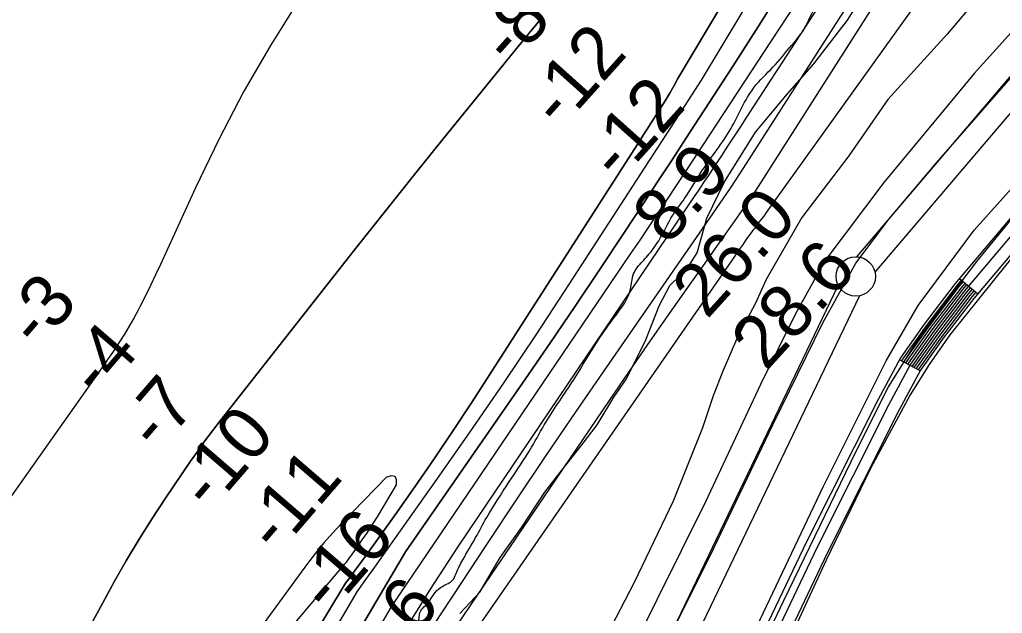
# Model space of a CAD drawing. Extents: x 3324104 to 3361979, y 612876 to 638273.
# Drawn here: x 3339241 to 3340489, y 622586 to 623340 of the extents above; entities that cross this region are included whole.
import ezdxf

# ---------------------------------------------------------------- set-up
doc = ezdxf.new("R2010")
doc.units = 0
for name, color, linetype in [('V-FLOD-BASE', 7, 'Continuous'), ('V-LEVE-TOET', 7, 'Continuous'), ('V-RIVR-EDGE', 7, 'Continuous'), ('V-RIVR-RANG', 7, 'Continuous'), ('V-ROAD-CNTR', 7, 'Continuous'), ('V-SITE-VEGE', 7, 'Continuous'), ('V-SURV-LINE', 7, 'Continuous'), ('V-TOPO-DPTH', 7, 'Continuous'), ('V-TOPO-MAJR', 7, 'Continuous'), ('V-TOPO-MINR', 7, 'Continuous'), ('V-TOPO-SHOR', 7, 'Continuous'), ('V-TOPO-WATR', 7, 'Continuous')]:
    doc.layers.add(name, color=color, linetype=linetype)

msp = doc.modelspace()

# ---------------------------------------------------------------- linework, layer by layer
at = {"layer": 'V-FLOD-BASE'}
msp.add_lwpolyline([(3339312.7, 620882.4), (3339404.9, 621089.8), (3339494.8, 621286.7), (3339586.4, 621493.4), (3339673.4, 621686.8), (3339741.3, 621847.5), (3339817, 622012.2), (3339917.6, 622243.4), (3340054, 622530.2), (3340122.8, 622669), (3340197.7, 622825.3), (3340261.4, 622955.1), (3340303.3, 623031), (3340345.5, 623087.2), (3340405.7, 623158.4), (3340514.4, 623282.9), (3340676.8, 623471.8)], dxfattribs=at)
at = {"layer": 'V-LEVE-TOET'}
for points in [[(3339416.8, 620890.1), (3339510.6, 621102.4), (3339609.6, 621324.5), (3339704.8, 621540.3), (3339774.2, 621702.3), (3339864.8, 621898.5), (3339953.2, 622091.1), (3340054.1, 622308.9), (3340149.8, 622511.3), (3340261.8, 622746.5), (3340341.6, 622906.9), (3340382.1, 622977.2), (3340453.4, 623072.9), (3340537.4, 623166.2), (3340664.9, 623312.1), (3340768.6, 623435.3)], [(3340579.5, 623411.9), (3340453.5, 623271.6), (3340338.8, 623133.2), (3340263.9, 623034), (3340226.3, 622965.8), (3340182, 622876.5), (3340112.2, 622727.8), (3339988.7, 622478.8), (3339907.9, 622310.7), (3339844.7, 622171.7), (3339774.1, 622016.8), (3339706.5, 621866.6), (3339613.4, 621655), (3339536.3, 621491.7), (3339464, 621327.6), (3339384.4, 621148.9), (3339298.2, 620958.3), (3339251.4, 620856.3)]]:
    msp.add_lwpolyline(points, dxfattribs=at)
at = {"layer": 'V-RIVR-EDGE'}
msp.add_spline([(3338849.5, 620833.7), (3338863.9, 620858.4), (3338873.2, 620877), (3338879.5, 620892.9), (3338887.7, 620911.1), (3338889.2, 620920.8), (3338889.3, 620930.9), (3338889.3, 620936.7), (3338892.8, 620944.8), (3338909.2, 620979.3), (3338928.6, 621017.7), (3338934.9, 621032.8), (3338933, 621036.3), (3338935.3, 621042.1), (3338955.2, 621075.8), (3338956.3, 621080), (3338951.3, 621082.4), (3338952.5, 621087.4), (3338954, 621094.8), (3338957.5, 621099.4), (3338963, 621104.8), (3338961.4, 621110.7), (3338960.7, 621117.6), (3338962.2, 621121.5), (3338980.9, 621151.3), (3338987.5, 621160.2), (3338994.6, 621173), (3339001.6, 621180.4), (3339008.6, 621185.8), (3339012.8, 621191.6), (3339013.6, 621197), (3339013.2, 621200.9), (3339009.8, 621206.7), (3339008.2, 621211.8), (3339009, 621213.7), (3339012.5, 621216.8), (3339014.8, 621221.1), (3339014.9, 621226.5), (3339018.4, 621227.2), (3339028, 621227.6), (3339031.2, 621232.3), (3339035.1, 621243.9), (3339039.8, 621256.3), (3339042.9, 621268.7), (3339045.6, 621270.2), (3339049.9, 621273.7), (3339052.6, 621276.8), (3339055.3, 621283.8), (3339058.5, 621297.7), (3339063.5, 621308.2), (3339066.3, 621319), (3339072.9, 621338), (3339074.5, 621340.7), (3339071.8, 621346.2), (3339071.4, 621350.8), (3339070.6, 621355.9), (3339070.6, 621360.9), (3339074.6, 621374.9), (3339080, 621383.4), (3339091.3, 621402), (3339101.8, 621418.6), (3339106.9, 621432.2), (3339108.9, 621448.5), (3339114.7, 621460.9), (3339121.7, 621472.9), (3339138.1, 621494.5), (3339146.6, 621512.7), (3339150.9, 621515.8), (3339154, 621517), (3339157.5, 621520.5), (3339162.2, 621524.7), (3339162.6, 621530.9), (3339163, 621535.2), (3339166.5, 621539.4), (3339173.9, 621548.4), (3339187.9, 621560), (3339202.3, 621575.4), (3339208.5, 621582), (3339220.9, 621601.4), (3339227.2, 621611.8), (3339228.3, 621618.4), (3339232.6, 621620.7), (3339234.6, 621627.7), (3339234.6, 621632.4), (3339233.8, 621643.2), (3339233.9, 621652.9), (3339235, 621660.7), (3339237.8, 621668.8), (3339245.6, 621681.6), (3339256.4, 621692), (3339259.6, 621702.1), (3339260.4, 621709.5), (3339267.8, 621721.9), (3339275.9, 621735.4), (3339287.3, 621761), (3339293.1, 621772.6), (3339304, 621793.5), (3339318, 621822.9), (3339329.7, 621836.9), (3339335.2, 621843.1), (3339330.5, 621848.9), (3339330.5, 621851.6), (3339333.3, 621855.9), (3339336.4, 621859.7), (3339342.2, 621865.5), (3339347.6, 621869.8), (3339357, 621888), (3339376.1, 621923.6), (3339382.7, 621941.8), (3339386.6, 621950.8), (3339393.2, 621962.8), (3339404.5, 621981.7), (3339427.1, 622013.9), (3339446.2, 622044.5), (3339464.1, 622073.5), (3339479.3, 622102.9), (3339498.8, 622140.9), (3339514.4, 622174.6), (3339531.9, 622205.2), (3339537.7, 622216), (3339537.7, 622219.9), (3339534.7, 622225.7), (3339534.7, 622228.8), (3339534.7, 622231.9), (3339539.7, 622235), (3339547.5, 622242.8), (3339556.8, 622254), (3339556.8, 622259.8), (3339555.7, 622266.4), (3339558.4, 622271.4), (3339563.9, 622273.7), (3339568.6, 622287.7), (3339574, 622293.9), (3339576.3, 622298.5), (3339576.4, 622305.1), (3339577.9, 622309.8), (3339583.4, 622315.6), (3339592.7, 622321.8), (3339605.1, 622339.6), (3339611, 622347.3), (3339621.1, 622355.4), (3339623.8, 622361.6), (3339624.2, 622367.4), (3339624.6, 622374.8), (3339628.1, 622381.4), (3339634.7, 622394.2), (3339652.6, 622417.8), (3339667, 622436.8), (3339680.3, 622456.9), (3339694.3, 622479), (3339705.2, 622499.1), (3339708.7, 622510.7), (3339714.6, 622523.5), (3339723.1, 622538.6), (3339729.4, 622550.2), (3339737.9, 622567.3), (3339738.7, 622571.9), (3339742.2, 622573.5), (3339746.9, 622573.8), (3339748.4, 622577.7), (3339749.2, 622585.1), (3339752, 622591.3), (3339757.8, 622596.7), (3339769.1, 622612.6), (3339778.4, 622620.3), (3339791.2, 622628), (3339795.5, 622636.5), (3339804.1, 622654), (3339820.4, 622682.2), (3339834.5, 622707.8), (3339891.3, 622796.9), (3339910, 622829.4), (3339944.6, 622882.4), (3339978.1, 622936.2), (3339998.7, 622964.9), (3340017.1, 622997.8), (3340021, 623017.2), (3340025.7, 623025.3), (3340038.9, 623040.4), (3340052.9, 623059.4), (3340070.8, 623091.9), (3340085.6, 623112.8), (3340108.6, 623149.2), (3340144.4, 623201.5), (3340174, 623254.2), (3340198.1, 623280.1), (3340221.4, 623307.2), (3340237, 623327.3), (3340244.4, 623342), (3340256.8, 623363.3), (3340272.8, 623384.6), (3340289.1, 623408.2), (3340302.8, 623428.7), (3340311.7, 623438.8), (3340319.5, 623450.4), (3340319.5, 623457.8), (3340325, 623465.9), (3340333.5, 623476.7), (3340341.3, 623483.3), (3340352.2, 623496.5), (3340367.4, 623520.1), (3340394.2, 623560), (3340400.1, 623574.3), (3340403.2, 623588.6), (3340409.1, 623600.7), (3340420.7, 623609.9), (3340437, 623624.6), (3340446.4, 623639.7), (3340451.1, 623650.6), (3340458.1, 623662.2), (3340477.1, 623683.9), (3340488, 623697)], degree=3, dxfattribs=at)
at = {"layer": 'V-ROAD-CNTR'}
for p, q in [((3340457.5, 622991.7), (3340434.6, 623011)), ((3340384.8, 622893.9), (3340358.4, 622908.1))]:
    msp.add_line(p, q, dxfattribs=at)
for points in [[(3340841.4, 623447.3), (3340749.1, 623337.6), (3340645.2, 623213.8), (3340452.8, 622986.1), (3340414.2, 622935.4), (3340385.2, 622894.7), (3340357.9, 622843.7), (3340267.3, 622663.5), (3340044.5, 622195.6), (3339766.5, 621575.5), (3339542.5, 621063.3), (3339452.6, 620864.7), (3339341.9, 620612.8)], [(3340726.1, 623356.9), (3340622.3, 623233.1), (3340429.4, 623004.9), (3340390, 622953.2), (3340359.7, 622910.5), (3340331.3, 622857.5), (3340240.4, 622676.7), (3340017.2, 622208.2), (3339739.1, 621587.6), (3339515.1, 621075.5), (3339425.2, 620876.9), (3339314.4, 620624.9)], [(3340737.6, 623347.3), (3340633.8, 623223.5), (3340441.1, 622995.5), (3340402.1, 622944.3), (3340372.4, 622902.6), (3340344.6, 622850.6), (3340253.9, 622670.1), (3340030.9, 622201.9), (3339752.8, 621581.6), (3339528.8, 621069.4), (3339438.9, 620870.8), (3339328.1, 620618.8)], [(3340436.9, 623009.1), (3340431.7, 623003), (3340392.5, 622951.4), (3340362.2, 622908.9), (3340361, 622906.7)], [(3340439.1, 623007.1), (3340434.1, 623001.1), (3340394.9, 622949.7), (3340364.8, 622907.3), (3340363.7, 622905.2)], [(3340441.4, 623005.2), (3340436.4, 622999.2), (3340397.3, 622947.9), (3340367.3, 622905.8), (3340366.3, 622903.8)], [(3340443.7, 623003.3), (3340438.7, 622997.4), (3340399.7, 622946.1), (3340369.9, 622904.2), (3340368.9, 622902.4)], [(3340446, 623001.3), (3340441.1, 622995.5), (3340402.1, 622944.3), (3340372.4, 622902.6), (3340371.6, 622901)], [(3340448.3, 622999.4), (3340443.4, 622993.6), (3340404.5, 622942.5), (3340375, 622901), (3340374.2, 622899.6)], [(3340450.6, 622997.5), (3340445.8, 622991.7), (3340407, 622940.8), (3340377.6, 622899.4), (3340376.9, 622898.1)], [(3340452.9, 622995.5), (3340448.1, 622989.9), (3340409.4, 622939), (3340380.1, 622897.8), (3340379.5, 622896.7)], [(3340455.2, 622993.6), (3340450.4, 622988), (3340411.8, 622937.2), (3340382.7, 622896.3), (3340382.2, 622895.3)]]:
    msp.add_lwpolyline(points, dxfattribs=at)
at = {"layer": 'V-SITE-VEGE'}
for p, q in [((3340292.6, 623339.4), (3340341.7, 623417.2)), ((3340476.5, 623390.1), (3340419.2, 623321.6)), ((3340249.7, 623283.9), (3340292.6, 623339.4)), ((3340419.2, 623321.6), (3340343.9, 623238.7)), ((3340216.4, 623245.9), (3340249.7, 623283.9)), ((3340175.8, 623197.4), (3340216.4, 623245.9)), ((3340343.9, 623238.7), (3340294.3, 623167.2)), ((3340136.2, 623134.2), (3340175.8, 623197.4)), ((3340294.3, 623167.2), (3340234.7, 623088.8)), ((3340114, 623088.1), (3340136.2, 623134.2)), ((3340101.7, 623043.9), (3340114, 623088.1)), ((3340234.7, 623088.8), (3340189.1, 623010.2)), ((3340090, 623025.2), (3340101.7, 623043.9)), ((3340080.6, 623015.5), (3340090, 623025.2)), ((3340066.9, 623002.4), (3340080.6, 623015.5)), ((3340189.1, 623010.2), (3340175.7, 622980.2)), ((3340053.6, 622976.6), (3340066.9, 623002.4)), ((3340036.4, 622933.3), (3340053.6, 622976.6)), ((3340175.7, 622980.2), (3340152.8, 622936.9)), ((3340011.9, 622883.8), (3340036.4, 622933.3)), ((3340152.8, 622936.9), (3340134.2, 622893.6)), ((3339995.9, 622860.8), (3340011.9, 622883.8)), ((3340134.2, 622893.6), (3340122.2, 622862.2)), ((3339974.6, 622825.4), (3339995.9, 622860.8)), ((3340122.2, 622862.2), (3340108.6, 622821.6)), ((3339955.7, 622800.4), (3339974.6, 622825.4)), ((3340108.6, 622821.6), (3340071.1, 622728.6)), ((3339930.3, 622768.5), (3339955.7, 622800.4)), ((3339908.4, 622740.1), (3339930.3, 622768.5)), ((3339879.2, 622695.6), (3339908.4, 622740.1)), ((3340071.1, 622728.6), (3340021.5, 622625.3)), ((3339851.5, 622656.8), (3339879.2, 622695.6)), ((3339825.8, 622612.9), (3339851.5, 622656.8)), ((3340021.5, 622625.3), (3339950.6, 622488)), ((3339800.5, 622586), (3339825.8, 622612.9))]:
    msp.add_line(p, q, dxfattribs=at)
at = {"layer": 'V-SURV-LINE'}
for points in [[(3340304.5, 623039), (3341044.9, 623909.4)], [(3341067.8, 623889.9), (3340327.3, 623019.5)], [(3339912.1, 622233.3), (3340280.8, 623002.5)], [(3340307.9, 622989.5), (3339939.2, 622220.3)]]:
    msp.add_lwpolyline(points, dxfattribs=at)
msp.add_circle((3340303, 623014), 25, dxfattribs=at)
at = {"layer": 'V-TOPO-DPTH'}
for points in [[(3340401.8, 623809.5), (3340077.1, 623265.5), (3340072.4, 623256.6), (3340067.5, 623247.7), (3340062.3, 623239), (3340057, 623230.3), (3340042.5, 623207.8), (3340038.3, 623201.1), (3340034, 623194.5), (3340029.8, 623187.9), (3340025.5, 623181.3), (3339815.8, 622854.5), (3339792, 622818.2), (3339767.9, 622782.2), (3339743.3, 622746.5), (3339718.2, 622711.1), (3339679.5, 622657.4), (3339673.5, 622649.1), (3339667.4, 622640.8), (3339661.3, 622632.5), (3339655.3, 622624.3), (3339316.8, 622062.3)], [(3339316.8, 622062.3), (3339655.3, 622624.3), (3339661.3, 622632.5), (3339667.4, 622640.8), (3339673.5, 622649.1), (3339679.5, 622657.4), (3339718.2, 622711.1), (3339743.3, 622746.5), (3339767.9, 622782.2), (3339792, 622818.2), (3339815.8, 622854.5), (3340025.5, 623181.3), (3340029.8, 623187.9), (3340034, 623194.5), (3340038.3, 623201.1), (3340042.5, 623207.8), (3340057, 623230.3), (3340062.3, 623239), (3340067.5, 623247.7), (3340072.4, 623256.6), (3340077.1, 623265.5), (3340401.8, 623809.5)], [(3339739.3, 622578.5), (3339750.8, 622597), (3339762.4, 622615.4), (3339774.1, 622633.7), (3339785.9, 622651.9), (3339797.9, 622670), (3339810, 622688.1), (3340099.2, 623116.7), (3340103.2, 623122.6), (3340107.2, 623128.6), (3340111.1, 623134.5), (3340115.1, 623140.4), (3340124, 623153.9), (3340132.4, 623166.6), (3340140.8, 623179.3), (3340149.1, 623192), (3340157.4, 623204.7), (3340161.9, 623211.8), (3340172.5, 623228), (3340183, 623244.3), (3340193.5, 623260.6), (3340204.1, 623276.8), (3340363.2, 623522.2)], [(3340211.5, 623382.7), (3340179.7, 623331.9), (3340147.4, 623281.5), (3340104.8, 623215.9), (3340087.3, 623189), (3340069.8, 623162.2), (3340052.3, 623135.4), (3340034.7, 623108.6), (3340008.7, 623068.9), (3339977.8, 623022.4), (3339946.8, 622976.1), (3339915.4, 622930), (3339883.8, 622884.1), (3339731.3, 622664.2), (3339344.2, 622006.7), (3339335.7, 621992)], [(3340211.5, 623382.7), (3340179.7, 623331.9), (3340147.4, 623281.5), (3340104.8, 623215.9), (3340087.3, 623189), (3340069.8, 623162.2), (3340052.3, 623135.4), (3340034.7, 623108.6), (3340008.7, 623068.9), (3339977.8, 623022.4), (3339946.8, 622976.1), (3339915.4, 622930), (3339883.8, 622884.1), (3339731.3, 622664.2), (3339344.2, 622006.7), (3339335.7, 621992)], [(3339189.5, 622322.2), (3339317.9, 622544.8), (3339332.4, 622572.2), (3339347.1, 622599.5), (3339361.9, 622626.7), (3339377.2, 622653.6), (3339393, 622680.2), (3339409.5, 622706.4), (3339426.5, 622732.3), (3339458.4, 622779.1), (3339467.5, 622792.2), (3339476.7, 622805.1), (3339486.2, 622817.8), (3339495.9, 622830.4), (3339670.1, 623051.9), (3339706.3, 623097.7), (3339742.6, 623143.4), (3339779.2, 623188.8), (3339816, 623234.2), (3339876.2, 623308.1), (3339882.9, 623316.3), (3339889.7, 623324.6), (3339896.4, 623332.9), (3339903.2, 623341.2)], [(3339903.2, 623341.2), (3339896.4, 623332.9), (3339889.7, 623324.6), (3339882.9, 623316.3), (3339876.2, 623308.1), (3339816, 623234.2), (3339779.2, 623188.8), (3339742.6, 623143.4), (3339706.3, 623097.7), (3339670.1, 623051.9), (3339495.9, 622830.4), (3339486.2, 622817.8), (3339476.7, 622805.1), (3339467.5, 622792.2), (3339458.4, 622779.1), (3339426.5, 622732.3), (3339409.5, 622706.4), (3339393, 622680.2), (3339377.2, 622653.6), (3339361.9, 622626.7), (3339347.1, 622599.5), (3339332.4, 622572.2), (3339317.9, 622544.8), (3339189.5, 622322.2)]]:
    msp.add_lwpolyline(points, dxfattribs=at)
at = {"layer": 'V-TOPO-MAJR'}
msp.add_lwpolyline([(3339801.4, 622536.7), (3340149.5, 623039.5), (3340153.1, 623044.8), (3340156.7, 623049.9), (3340160.4, 623055.1), (3340164.1, 623060.3), (3340170, 623068.6), (3340171.5, 623070.6), (3340173, 623072.6), (3340174.6, 623074.6), (3340176.1, 623076.6), (3340179.7, 623081.5), (3340182.3, 623084.9), (3340184.9, 623088.4), (3340187.4, 623091.8), (3340189.9, 623095.3), (3340609.4, 623680.9)], dxfattribs=at)
at = {"layer": 'V-TOPO-MINR'}
for points in [[(3339316.8, 622062.3), (3339655.3, 622624.3), (3339661.3, 622632.5), (3339667.4, 622640.8), (3339673.5, 622649.1), (3339679.5, 622657.4), (3339718.2, 622711.1), (3339743.3, 622746.5), (3339767.9, 622782.2), (3339792, 622818.2), (3339815.8, 622854.5), (3340025.5, 623181.3), (3340029.8, 623187.9), (3340034, 623194.5), (3340038.3, 623201.1), (3340042.5, 623207.8), (3340057, 623230.3), (3340062.3, 623239), (3340067.5, 623247.7), (3340072.4, 623256.6), (3340077.1, 623265.5), (3340401.8, 623809.5)], [(3339025.5, 621422.5), (3339322.3, 622021.7), (3339338.1, 622048), (3339360.1, 622084.8), (3339370.6, 622102.8), (3339669.8, 622613.3), (3339681.1, 622629), (3339692.2, 622644.7), (3339703.4, 622660.4), (3339769, 622753.1), (3339812.5, 622815.4), (3339855.6, 622878), (3339897.9, 622941.2), (3339939.7, 623004.7), (3340030.3, 623144.4), (3340041.3, 623161.2), (3340052.2, 623178.1), (3340063.1, 623195), (3340074, 623211.9), (3340107.1, 623263.2), (3340432.9, 623805.1)], [(3339423.9, 621920.4), (3339761.8, 622517), (3339770.4, 622530.6), (3339779, 622544.1), (3339787.9, 622557.5), (3339796.8, 622570.9), (3339982.4, 622844.6), (3340010.3, 622885.5), (3340038.3, 622926.2), (3340066.6, 622966.8), (3340095.1, 623007.2), (3340109, 623026.8), (3340130.6, 623057.4), (3340152.1, 623088), (3340173.6, 623118.7), (3340495.5, 623624)], [(3339739.3, 622578.5), (3339750.8, 622597), (3339762.4, 622615.4), (3339774.1, 622633.7), (3339785.9, 622651.9), (3339797.9, 622670), (3339810, 622688.1), (3340099.2, 623116.7), (3340103.2, 623122.6), (3340107.2, 623128.6), (3340111.1, 623134.5), (3340115.1, 623140.4), (3340124, 623153.9), (3340132.4, 623166.6), (3340140.8, 623179.3), (3340149.1, 623192), (3340157.4, 623204.7), (3340161.9, 623211.8), (3340172.5, 623228), (3340183, 623244.3), (3340193.5, 623260.6), (3340204.1, 623276.8), (3340363.2, 623522.2)], [(3338742.8, 620501.6), (3339044.3, 621319.6), (3339375.8, 621881.1), (3339386.5, 621898.5), (3339397.3, 621915.8), (3339408.3, 621933), (3339419.4, 621950.1), (3339730.5, 622511.9), (3339745.4, 622536.1), (3339760.5, 622560.2), (3339775.9, 622584.2), (3339791.4, 622608), (3339834.8, 622673.6), (3339872.3, 622730.1), (3339910.1, 622786.4), (3339948.2, 622842.4), (3339986.6, 622898.3), (3340104.7, 623069.1), (3340117.8, 623088.1), (3340130.9, 623107.2), (3340143.9, 623126.3), (3340156.9, 623145.4), (3340379.3, 623493.6)], [(3339351.9, 621958.9), (3339448.5, 622129.6), (3339482.1, 622189.3), (3339515.6, 622249), (3339548.9, 622308.8), (3339582, 622368.7), (3339712.1, 622592.3), (3339716.3, 622598.5), (3339720.4, 622604.6), (3339724.6, 622610.8), (3340017.4, 623042.9), (3340029.1, 623060.2), (3340040.7, 623077.4), (3340052.3, 623094.7), (3340063.9, 623112.1), (3340075.4, 623129.4), (3340086.9, 623146.8), (3340098.4, 623164.2), (3340109.8, 623181.6), (3340186.3, 623298.3), (3340235.7, 623374.2)], [(3339595.7, 623365.4), (3339559.9, 623307.4), (3339525.8, 623248.5), (3339494.3, 623188.1), (3339464.6, 623126.7), (3339420.1, 623029.1), (3339413.9, 623015.8), (3339407.6, 623002.6), (3339401.1, 622989.5), (3339394.4, 622976.4), (3339391.8, 622971.2), (3339386.2, 622960.8), (3339380.5, 622950.7), (3339374.4, 622940.7), (3339368.1, 622930.8), (3339359.3, 622917.4), (3339357.2, 622914.4), (3339355.1, 622911.3), (3339353, 622908.3), (3339350.9, 622905.2), (3339148, 622618.3)], [(3339903.2, 623341.2), (3339896.4, 623332.9), (3339889.7, 623324.6), (3339882.9, 623316.3), (3339876.2, 623308.1), (3339816, 623234.2), (3339779.2, 623188.8), (3339742.6, 623143.4), (3339706.3, 623097.7), (3339670.1, 623051.9), (3339495.9, 622830.4), (3339486.2, 622817.8), (3339476.7, 622805.1), (3339467.5, 622792.2), (3339458.4, 622779.1), (3339426.5, 622732.3), (3339409.5, 622706.4), (3339393, 622680.2), (3339377.2, 622653.6), (3339361.9, 622626.7), (3339347.1, 622599.5), (3339332.4, 622572.2), (3339317.9, 622544.8), (3339189.5, 622322.2)], [(3339655.9, 622650.8), (3339657.6, 622652.9), (3339659.2, 622655.1), (3339669.8, 622669.6), (3339676.5, 622679.2), (3339683.1, 622688.9), (3339689.4, 622698.7), (3339695.6, 622708.6), (3339720.1, 622749.2), (3339720, 622755.7), (3339718.1, 622759.9), (3339713.5, 622760.6), (3339707.3, 622759.1), (3339650, 622700.2), (3339638.6, 622688), (3339627.5, 622675.4), (3339617, 622662.4), (3339606.8, 622649.2), (3339522.9, 622534.7)], [(3339554.5, 622530.5), (3339652.5, 622646.6), (3339654.3, 622648.7), (3339655.9, 622650.8)]]:
    msp.add_lwpolyline(points, dxfattribs=at)
at = {"layer": 'V-TOPO-SHOR'}
for points in [[(3340795.8, 623437.1), (3340661, 623279.3), (3340562.3, 623162.4), (3340456.4, 623032.9), (3340385.1, 622939.3), (3340344.1, 622873.9), (3340296.7, 622778.4), (3340211.5, 622601.9), (3340121.1, 622412.8), (3340044, 622250.2), (3339952.6, 622050.5), (3339899, 621930.4), (3339806.1, 621724.5), (3339741.3, 621575.7), (3339663.8, 621396.2), (3339564.1, 621173.4), (3339484.4, 620991.8), (3339417.4, 620836.8)], [(3340760.8, 623351.2), (3340684.3, 623258), (3340594.4, 623148.3), (3340495.3, 623030.3), (3340422.3, 622940), (3340396.3, 622902.3), (3340372, 622863.4), (3340321.7, 622769.8), (3340265.3, 622653.4), (3340218.5, 622552.1), (3340159.4, 622431.6), (3340100.3, 622307.8), (3340037.8, 622174.8), (3339990.6, 622072), (3339936.4, 621953.5), (3339865.2, 621793.9), (3339806.1, 621657.6), (3339762.5, 621558.5), (3339709.2, 621430.6), (3339642.6, 621279.3), (3339531.8, 621032.3), (3339467.1, 620885.2)]]:
    msp.add_lwpolyline(points, dxfattribs=at)
at = {"layer": 'V-TOPO-WATR'}
msp.add_lwpolyline([(3339335.7, 621992), (3339344.2, 622006.7), (3339731.3, 622664.2), (3339883.8, 622884.1), (3339915.4, 622930), (3339946.8, 622976.1), (3339977.8, 623022.4), (3340008.7, 623068.9), (3340034.7, 623108.6), (3340052.3, 623135.4), (3340069.8, 623162.2), (3340087.3, 623189), (3340104.8, 623215.9), (3340147.4, 623281.5), (3340179.7, 623331.9), (3340211.5, 623382.7)], dxfattribs=at)

# ---------------------------------------------------------------- texts
at = {"layer": 'V-RIVR-RANG'}
for s, rotation, p in [('-8', 48.1109, (3339865.4, 623279.5)), ('-12', 48.1109, (3339928.1, 623199.6)), ('-12', 48.1109, (3340002.4, 623132.6)), ('8.9', 47.8283, (3340063.9, 623052.1)), ('26.0', 47.8283, (3340114.1, 622958.5)), ('28.6', 47.8283, (3340189.1, 622892.4)), ('-3', 49.2162, (3339265.2, 622920.1)), ('-4', 49.2162, (3339343, 622857.2)), ('-7', 49.2162, (3339416.7, 622789.5)), ('-10', 49.2162, (3339483.5, 622713.8)), ('-11', 49.2162, (3339568.7, 622659.5)), ('-16', 49.2162, (3339635.1, 622583.4)), ('8.6', 48.9283, (3339695.4, 622500.9))]:
    msp.add_text(s, height=67, rotation=rotation, dxfattribs=at).set_placement(p)

doc.saveas('drawing.dxf')
